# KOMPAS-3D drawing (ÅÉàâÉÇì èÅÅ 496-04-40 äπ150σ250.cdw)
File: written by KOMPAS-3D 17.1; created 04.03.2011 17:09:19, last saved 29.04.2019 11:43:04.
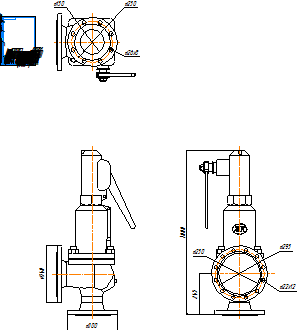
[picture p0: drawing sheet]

Sheet 1: A4, portrait

Title block, sheet 1: name: Прегран Ду 150х250; material: Внимание! Данный продукт является объектом авторского права ООО «Торговый Дом АДЛ». / Запрещается изменение, копирование, распространение / (в том числе путем копирования на другие сайты и ресурсы в Интернете) / или любое иное использование информации и объектов без предварительного / согласия правообладателя (ООО «Торговый Дом АДЛ»).; scale: 1:1; sheets: 1; organisation: ООО "Торговый дом АДЛ"; sheet format: A4; stored path: C:\Users\tra\Desktop\2д чертежи\Предохранительные клапаны ПРЕГРАН\ПРЕГРАН 496\ПРЕГРАН КПП 496-04-40\KOMPAS 2D\Прегран Ду 150х250.cdw

Views: Спереди 1, Проекционный вид 2, Проекционный вид 3
Dimensions and other numbers on the sheet: 300; 340; 245; 1000; 295; 22; 250; 150; 26; 1:1; 1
